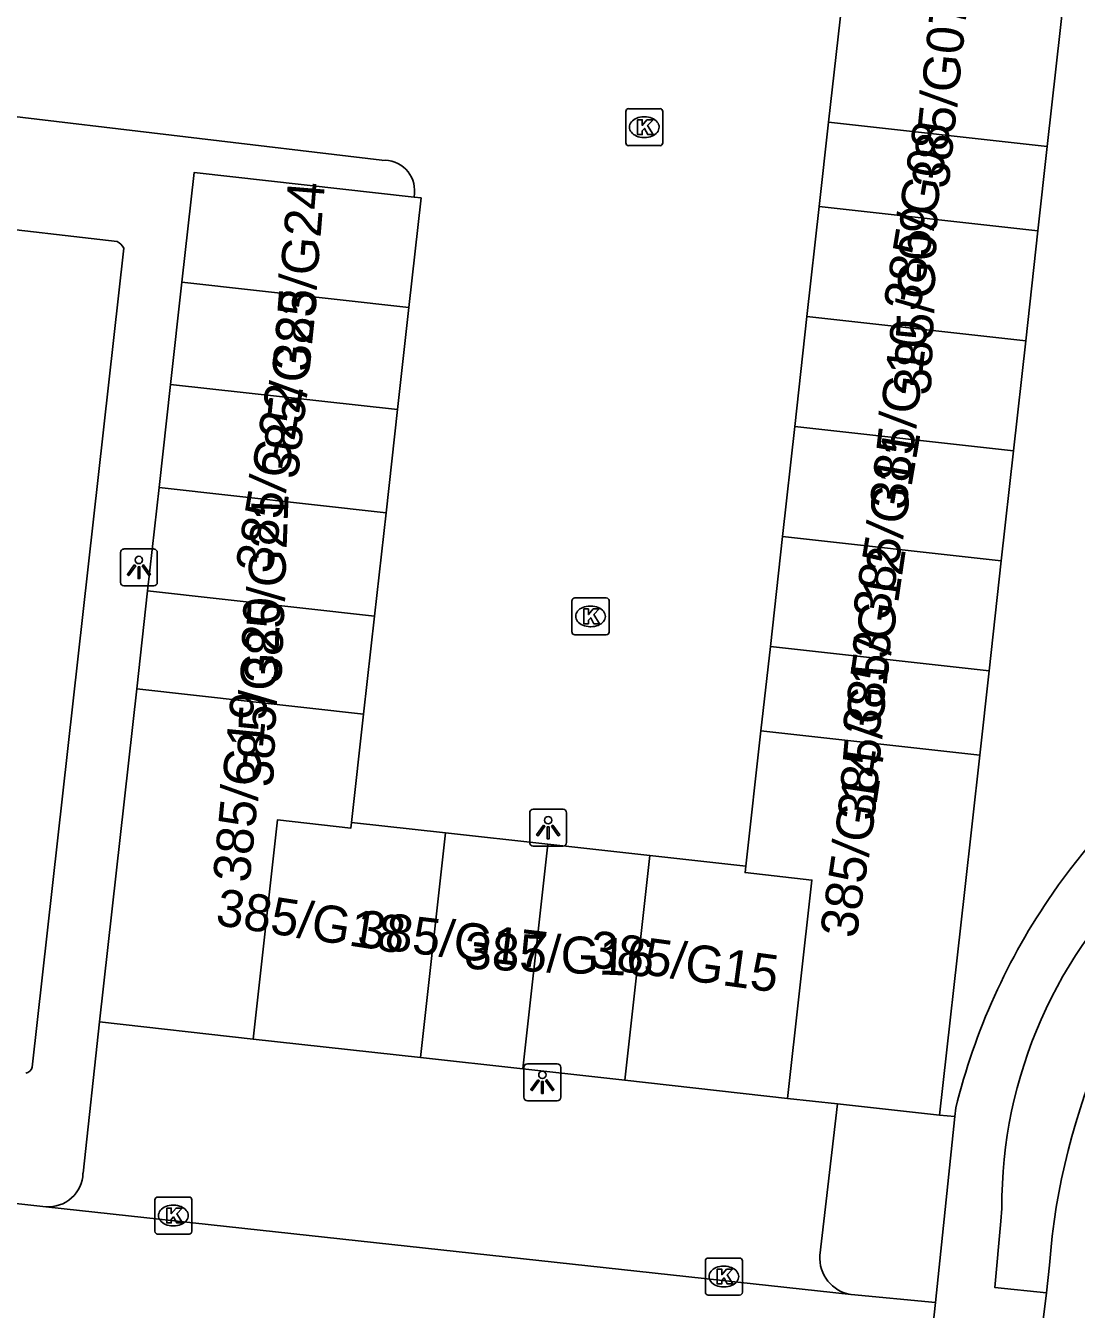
# Model space of a CAD drawing. Extents: x 162026 to 163499, y 387297 to 388169.
# Drawn here: x 162149.27 to 162177.68, y 387793.2 to 387827.91 of the extents above; entities that cross this region are included whole.
import ezdxf

# ---------------------------------------------------------------- set-up
doc = ezdxf.new("R2010")
doc.units = 0
for name, color, linetype in [('IMGEO_Groenvoorziening', 7, 'Continuous'), ('IMGEO_Kolk', 7, 'Continuous'), ('IMGEO_Lichtpunt', 7, 'Continuous'), ('IMGEO_Pand', 7, 'Continuous'), ('IMGEO_Pand_nummerreeks', 7, 'Continuous'), ('IMGEO_Parkeervlak_open', 7, 'Continuous'), ('IMGEO_Rijbaan_lokaal_open', 7, 'Continuous'), ('IMGEO_Voetpad_open', 7, 'Continuous')]:
    doc.layers.add(name, color=color, linetype=linetype)

msp = doc.modelspace()

# ---------------------------------------------------------------- linework, layer by layer
at = {"layer": 'IMGEO_Groenvoorziening'}
msp.add_lwpolyline([(162174.399, 387798.411), (162173.985, 387798.447)], dxfattribs=at)
at = {"layer": 'IMGEO_Kolk'}
for p, q in [((162165.499, 387824.744), (162165.499, 387825.596)), ((162165.574, 387825.67), (162166.426, 387825.67)), ((162166.5, 387825.596), (162166.5, 387824.744)), ((162165.987, 387825.45), (162166.012, 387825.45)), ((162166.01, 387824.89), (162165.985, 387824.89)), ((162166.426, 387824.67), (162165.574, 387824.67)), ((162164.045, 387811.514), (162164.045, 387812.366)), ((162164.12, 387812.44), (162164.972, 387812.44)), ((162165.046, 387812.366), (162165.046, 387811.514)), ((162164.533, 387812.22), (162164.558, 387812.22)), ((162164.556, 387811.66), (162164.531, 387811.66)), ((162164.972, 387811.44), (162164.12, 387811.44)), ((162152.766, 387795.31), (162152.766, 387796.162)), ((162152.841, 387796.236), (162153.693, 387796.236)), ((162153.767, 387796.162), (162153.767, 387795.31)), ((162153.254, 387796.016), (162153.279, 387796.016)), ((162153.277, 387795.456), (162153.252, 387795.456)), ((162153.693, 387795.236), (162152.841, 387795.236)), ((162167.651, 387793.66), (162167.651, 387794.512)), ((162167.726, 387794.586), (162168.578, 387794.586)), ((162168.139, 387794.366), (162168.164, 387794.366)), ((162168.652, 387794.512), (162168.652, 387793.66)), ((162168.162, 387793.806), (162168.137, 387793.806)), ((162168.578, 387793.586), (162167.726, 387793.586))]:
    msp.add_line(p, q, dxfattribs=at)
for points in [[(162165.499, 387824.744), (162165.499, 387825.596)], [(162165.574, 387825.67), (162166.426, 387825.67)], [(162166.5, 387825.596), (162166.5, 387824.744)], [(162165.82, 387825.37), (162165.943, 387825.37), (162165.943, 387825.219), (162166.073, 387825.37), (162166.237, 387825.37), (162166.091, 387825.219), (162166.244, 387824.97), (162166.092, 387824.97), (162166.007, 387825.134), (162165.943, 387825.067), (162165.943, 387824.97), (162165.82, 387824.97), (162165.82, 387825.37)], [(162166.426, 387824.67), (162165.574, 387824.67)], [(162164.045, 387811.514), (162164.045, 387812.366)], [(162164.12, 387812.44), (162164.972, 387812.44)], [(162165.046, 387812.366), (162165.046, 387811.514)], [(162164.366, 387812.14), (162164.489, 387812.14), (162164.489, 387811.989), (162164.619, 387812.14), (162164.783, 387812.14), (162164.637, 387811.989), (162164.79, 387811.74), (162164.638, 387811.74), (162164.553, 387811.904), (162164.489, 387811.837), (162164.489, 387811.74), (162164.366, 387811.74), (162164.366, 387812.14)], [(162164.972, 387811.44), (162164.12, 387811.44)], [(162152.766, 387795.31), (162152.766, 387796.162)], [(162152.841, 387796.236), (162153.693, 387796.236)], [(162153.767, 387796.162), (162153.767, 387795.31)], [(162153.087, 387795.936), (162153.21, 387795.936), (162153.21, 387795.785), (162153.34, 387795.936), (162153.504, 387795.936), (162153.358, 387795.785), (162153.511, 387795.536), (162153.359, 387795.536), (162153.274, 387795.7), (162153.21, 387795.633), (162153.21, 387795.536), (162153.087, 387795.536), (162153.087, 387795.936)], [(162153.693, 387795.236), (162152.841, 387795.236)], [(162167.651, 387793.66), (162167.651, 387794.512)], [(162167.726, 387794.586), (162168.578, 387794.586)], [(162168.652, 387794.512), (162168.652, 387793.66)], [(162167.972, 387794.286), (162168.095, 387794.286), (162168.095, 387794.135), (162168.225, 387794.286), (162168.389, 387794.286), (162168.243, 387794.135), (162168.396, 387793.886), (162168.244, 387793.886), (162168.159, 387794.05), (162168.095, 387793.983), (162168.095, 387793.886), (162167.972, 387793.886), (162167.972, 387794.286)], [(162168.578, 387793.586), (162167.726, 387793.586)]]:
    msp.add_lwpolyline(points, dxfattribs=at)
for centre, start, end in [((162165.576, 387825.594), 91.552, 178.448), ((162165.576, 387825.594), 91.552, 178.448), ((162166.424, 387825.594), 1.552, 88.448), ((162166.424, 387825.594), 1.552, 88.448), ((162165.576, 387824.746), 181.552, 268.448), ((162165.576, 387824.746), 181.552, 268.448), ((162166.424, 387824.746), 271.552, 358.448), ((162166.424, 387824.746), 271.552, 358.448), ((162164.122, 387812.364), 91.552, 178.448), ((162164.122, 387812.364), 91.552, 178.448), ((162164.97, 387812.364), 1.552, 88.448), ((162164.97, 387812.364), 1.552, 88.448), ((162164.122, 387811.516), 181.552, 268.448), ((162164.122, 387811.516), 181.552, 268.448), ((162164.97, 387811.516), 271.552, 358.448), ((162164.97, 387811.516), 271.552, 358.448), ((162152.843, 387796.16), 91.552, 178.448), ((162152.843, 387796.16), 91.552, 178.448), ((162153.691, 387796.16), 1.552, 88.448), ((162153.691, 387796.16), 1.552, 88.448), ((162152.843, 387795.312), 181.552, 268.448), ((162152.843, 387795.312), 181.552, 268.448), ((162153.691, 387795.312), 271.552, 358.448), ((162153.691, 387795.312), 271.552, 358.448), ((162167.728, 387794.51), 91.552, 178.448), ((162167.728, 387794.51), 91.552, 178.448), ((162168.576, 387794.51), 1.552, 88.448), ((162168.576, 387794.51), 1.552, 88.448), ((162167.728, 387793.662), 181.552, 268.448), ((162167.728, 387793.662), 181.552, 268.448), ((162168.576, 387793.662), 271.552, 358.448), ((162168.576, 387793.662), 271.552, 358.448)]:
    msp.add_arc(centre, 0.0765, start, end, dxfattribs=at)
for centre, major_axis, ratio, start_param, end_param in [((162165.986, 387825.17), (-0.387, 0.002), 0.722429, 4.712389, 7.853982), ((162166.011, 387825.17), (-0.39, 0.002), 0.717154, 1.570796, 4.712389), ((162164.532, 387811.94), (-0.387, 0.002), 0.722429, 4.712389, 7.853982), ((162164.557, 387811.94), (-0.39, 0.002), 0.717154, 1.570796, 4.712389), ((162153.253, 387795.736), (-0.387, 0.002), 0.722429, 4.712389, 7.853982), ((162153.278, 387795.736), (-0.39, 0.002), 0.717154, 1.570796, 4.712389), ((162168.138, 387794.086), (-0.387, 0.002), 0.722429, 4.712389, 7.853982), ((162168.163, 387794.086), (-0.39, 0.002), 0.717154, 1.570796, 4.712389)]:
    msp.add_ellipse(centre, major_axis=major_axis, ratio=ratio, start_param=start_param, end_param=end_param, dxfattribs=at)
at = {"layer": 'IMGEO_Lichtpunt'}
for p, q in [((162152.739, 387813.762), (162151.931, 387813.762)), ((162152.739, 387813.762), (162151.931, 387813.762)), ((162151.837, 387813.667), (162151.837, 387812.86)), ((162151.837, 387813.667), (162151.837, 387812.86)), ((162152.833, 387812.86), (162152.833, 387813.667)), ((162152.833, 387812.86), (162152.833, 387813.667)), ((162151.931, 387812.766), (162152.739, 387812.766)), ((162151.931, 387812.766), (162152.739, 387812.766)), ((162162.902, 387806.628), (162162.902, 387805.821)), ((162162.902, 387806.628), (162162.902, 387805.821)), ((162163.804, 387806.723), (162162.996, 387806.723)), ((162163.804, 387806.723), (162162.996, 387806.723)), ((162163.898, 387805.821), (162163.898, 387806.628)), ((162163.898, 387805.821), (162163.898, 387806.628)), ((162162.996, 387805.727), (162163.804, 387805.727)), ((162162.996, 387805.727), (162163.804, 387805.727)), ((162162.745, 387799.743), (162162.745, 387798.936)), ((162162.745, 387799.743), (162162.745, 387798.936)), ((162163.647, 387799.838), (162162.839, 387799.838)), ((162163.647, 387799.838), (162162.839, 387799.838)), ((162163.741, 387798.936), (162163.741, 387799.743)), ((162163.741, 387798.936), (162163.741, 387799.743)), ((162162.839, 387798.842), (162163.647, 387798.842)), ((162162.839, 387798.842), (162163.647, 387798.842))]:
    msp.add_line(p, q, dxfattribs=at)
for points in [[(162152.211, 387813.331), (162152.25, 387813.303), (162152.062, 387813.041), (162152.024, 387813.068), (162152.211, 387813.331)], [(162152.313, 387813.283), (162152.36, 387813.283), (162152.36, 387812.961), (162152.313, 387812.961), (162152.313, 387813.283)], [(162152.423, 387813.303), (162152.461, 387813.33), (162152.648, 387813.068), (162152.609, 387813.04), (162152.423, 387813.303)], [(162163.276, 387806.292), (162163.315, 387806.264), (162163.127, 387806.002), (162163.089, 387806.029), (162163.276, 387806.292)], [(162163.378, 387806.244), (162163.425, 387806.244), (162163.425, 387805.922), (162163.378, 387805.922), (162163.378, 387806.244)], [(162163.488, 387806.264), (162163.526, 387806.291), (162163.713, 387806.029), (162163.674, 387806.001), (162163.488, 387806.264)], [(162163.119, 387799.407), (162163.158, 387799.379), (162162.97, 387799.117), (162162.932, 387799.144), (162163.119, 387799.407)], [(162163.221, 387799.359), (162163.268, 387799.359), (162163.268, 387799.037), (162163.221, 387799.037), (162163.221, 387799.359)], [(162163.331, 387799.379), (162163.369, 387799.406), (162163.556, 387799.144), (162163.517, 387799.116), (162163.331, 387799.379)]]:
    msp.add_lwpolyline(points, dxfattribs=at)
for centre in [(162152.336, 387813.465), (162163.401, 387806.426), (162163.244, 387799.541)]:
    msp.add_circle(centre, 0.0994, dxfattribs=at)
for centre, start, end in [((162151.931, 387813.667), 90, 180), ((162151.931, 387813.667), 90, 180), ((162152.739, 387813.667), 0, 90), ((162152.739, 387813.667), 0, 90), ((162151.931, 387812.86), 180, 270), ((162151.931, 387812.86), 180, 270), ((162152.739, 387812.86), 270, 0), ((162152.739, 387812.86), 270, 360), ((162162.996, 387806.628), 90, 180), ((162162.996, 387806.628), 90, 180), ((162163.804, 387806.628), 0, 90), ((162163.804, 387806.628), 0, 90), ((162162.996, 387805.821), 180, 270), ((162162.996, 387805.821), 180, 270), ((162163.804, 387805.821), 270, 0), ((162163.804, 387805.821), 270, 360), ((162162.839, 387799.743), 90, 180), ((162162.839, 387799.743), 90, 180), ((162163.647, 387799.743), 0, 90), ((162163.647, 387799.743), 0, 90), ((162162.839, 387798.936), 180, 270), ((162162.839, 387798.936), 180, 270), ((162163.647, 387798.936), 270, 0), ((162163.647, 387798.936), 270, 360)]:
    msp.add_arc(centre, 0.0946, start, end, dxfattribs=at)
at = {"layer": 'IMGEO_Pand'}
for points in [[(162177.973, 387834.328), (162177.854, 387833.262), (162176.897, 387824.645)], [(162171.391, 387828.971), (162170.983, 387825.303)], [(162170.983, 387825.303), (162170.73, 387823.024)], [(162176.897, 387824.645), (162170.983, 387825.303)], [(162176.897, 387824.645), (162176.643, 387822.366)], [(162159.777, 387823.278), (162153.827, 387823.94), (162153.498, 387820.978)], [(162159.777, 387823.278), (162159.965, 387823.257), (162159.635, 387820.293)], [(162170.73, 387823.024), (162170.399, 387820.05)], [(162170.73, 387823.024), (162176.643, 387822.366)], [(162176.643, 387822.366), (162176.313, 387819.393)], [(162153.498, 387820.978), (162153.191, 387818.215)], [(162159.635, 387820.293), (162153.498, 387820.978)], [(162159.328, 387817.53), (162159.635, 387820.293)], [(162170.399, 387820.05), (162170.069, 387817.076)], [(162170.399, 387820.05), (162176.313, 387819.393)], [(162176.313, 387819.393), (162175.983, 387816.419)], [(162153.191, 387818.215), (162152.88, 387815.421)], [(162153.191, 387818.215), (162159.328, 387817.53)], [(162159.018, 387814.739), (162159.328, 387817.53)], [(162170.069, 387817.076), (162169.738, 387814.102)], [(162175.983, 387816.419), (162170.069, 387817.076)], [(162175.983, 387816.419), (162175.652, 387813.445)], [(162152.88, 387815.421), (162152.57, 387812.63)], [(162152.88, 387815.421), (162159.018, 387814.739)], [(162159.018, 387814.739), (162158.708, 387811.948)], [(162169.738, 387814.102), (162169.408, 387811.128)], [(162175.652, 387813.445), (162169.738, 387814.102)], [(162175.652, 387813.445), (162175.322, 387810.471)], [(162152.57, 387812.63), (162152.275, 387809.976)], [(162158.708, 387811.948), (162152.57, 387812.63)], [(162158.412, 387809.293), (162158.708, 387811.948)], [(162169.408, 387811.128), (162169.155, 387808.848)], [(162169.408, 387811.128), (162175.322, 387810.471)], [(162175.322, 387810.471), (162175.068, 387808.19)], [(162152.275, 387809.976), (162151.274, 387800.971)], [(162152.275, 387809.976), (162158.412, 387809.293)], [(162158.412, 387809.293), (162158.087, 387806.366)], [(162168.747, 387805.181), (162169.155, 387808.848)], [(162169.155, 387808.848), (162175.068, 387808.19)], [(162175.068, 387808.19), (162174.655, 387804.471), (162173.985, 387798.447)], [(162158.087, 387806.366), (162158.068, 387806.216), (162156.081, 387806.437), (162155.422, 387800.51)], [(162160.629, 387806.083), (162158.087, 387806.366)], [(162160.629, 387806.083), (162159.953, 387800.006)], [(162163.39, 387805.777), (162160.629, 387806.083)], [(162162.714, 387799.7), (162163.39, 387805.777)], [(162166.151, 387805.47), (162163.39, 387805.777)], [(162165.475, 387799.393), (162166.151, 387805.47)], [(162166.151, 387805.47), (162168.747, 387805.181)], [(162169.875, 387798.904), (162170.532, 387804.81), (162168.726, 387805.011), (162168.747, 387805.181)], [(162155.422, 387800.51), (162151.274, 387800.971)], [(162159.953, 387800.006), (162155.422, 387800.51)], [(162162.714, 387799.7), (162159.953, 387800.006)], [(162165.475, 387799.393), (162162.714, 387799.7)], [(162169.875, 387798.904), (162165.475, 387799.393)], [(162171.221, 387798.754), (162169.875, 387798.904)], [(162173.985, 387798.447), (162171.221, 387798.754)]]:
    msp.add_lwpolyline(points, dxfattribs=at)
at = {"layer": 'IMGEO_Parkeervlak_open'}
for points in [[(162151.75, 387822.08), (162147.838, 387822.528)], [(162149.449, 387799.753), (162151.927, 387821.901)], [(162151.274, 387800.971), (162150.824, 387796.88)], [(162171.221, 387798.754), (162170.746, 387794.657)]]:
    msp.add_lwpolyline(points, dxfattribs=at)
for centre, radius, start, end in [((162151.513, 387821.669), 0.474, 29.2912, 60.065), ((162149.254, 387799.784), 0.197, 275.7663, 350.8643), ((162149.888, 387796.908), 0.936, 265.6436, 358.312), ((162171.751, 387794.592), 1.007, 176.3125, 260.7294)]:
    msp.add_arc(centre, radius, start, end, dxfattribs=at)
at = {"layer": 'IMGEO_Rijbaan_lokaal_open'}
for points in [[(162148.279, 387825.537), (162158.908, 387824.273)], [(162159.786, 387823.383), (162159.777, 387823.278)], [(162149.817, 387795.974), (162145.027, 387796.502)], [(162149.817, 387795.974), (162171.589, 387793.598)], [(162176.954, 387794.397), (162176.873, 387793.647)], [(162171.589, 387793.598), (162173.877, 387793.382)], [(162176.873, 387793.647), (162176.767, 387792.767), (162176.029, 387786.281)], [(162173.877, 387793.382), (162173.226, 387787.405)]]:
    msp.add_lwpolyline(points, dxfattribs=at)
for centre, radius, start, end in [((162158.967, 387823.453), 0.822, 355.1177, 94.1045), ((162195.063, 387793.031), 18.161, 136.1983, 175.6852)]:
    msp.add_arc(centre, radius, start, end, dxfattribs=at)
at = {"layer": 'IMGEO_Voetpad_open'}
for points in [[(162174.423, 387798.647), (162174.399, 387798.411)], [(162174.399, 387798.411), (162173.877, 387793.382)], [(162176.873, 387793.647), (162175.477, 387793.792), (162175.642, 387795.586), (162175.666, 387795.93)]]:
    msp.add_lwpolyline(points, dxfattribs=at)
for centre, radius, start, end in [((162191.407, 387794.495), 17.477, 130.9104, 145.2692), ((162188.185, 387795.99), 12.519, 132.1359, 180.2763), ((162191.436, 387794.462), 17.52, 145.2363, 166.181)]:
    msp.add_arc(centre, radius, start, end, dxfattribs=at)

# ---------------------------------------------------------------- texts
at = {"layer": 'IMGEO_Pand_nummerreeks'}
for s, rotation, p in [('385/G07', 84.1226, (162174.224, 387823.485)), ('385/G08', 80.5377, (162173.445, 387820.16)), ('385/G24', 85.3306, (162156.948, 387818.539)), ('385/G09', 87.8789, (162173.746, 387817.906)), ('385/G23', 84.0531, (162156.635, 387815.635)), ('385/G10', 83.2902, (162173.083, 387814.796)), ('385/G22', 80.3401, (162155.923, 387813.068)), ('385/G11', 80.3625, (162172.611, 387811.82)), ('385/G21', 87.7974, (162156.188, 387810.111)), ('385/G12', 81.7241, (162172.336, 387808.668)), ('385/G20', 87.6627, (162155.962, 387807.311)), ('385/G13', 84.8056, (162172.219, 387806.395)), ('385/G19', 84.4007, (162155.327, 387804.719)), ('385/G14', 81.509, (162171.734, 387803.21)), ('385/G18', 351.2026, (162154.379, 387803.6)), ('385/G17', 353.1572, (162158.213, 387803.015)), ('385/G16', 357.6141, (162161.119, 387802.41)), ('385/G15', 352.1709, (162164.473, 387802.466))]:
    msp.add_text(s, height=1, rotation=rotation, dxfattribs=at).set_placement(p)

doc.saveas('drawing.dxf')
